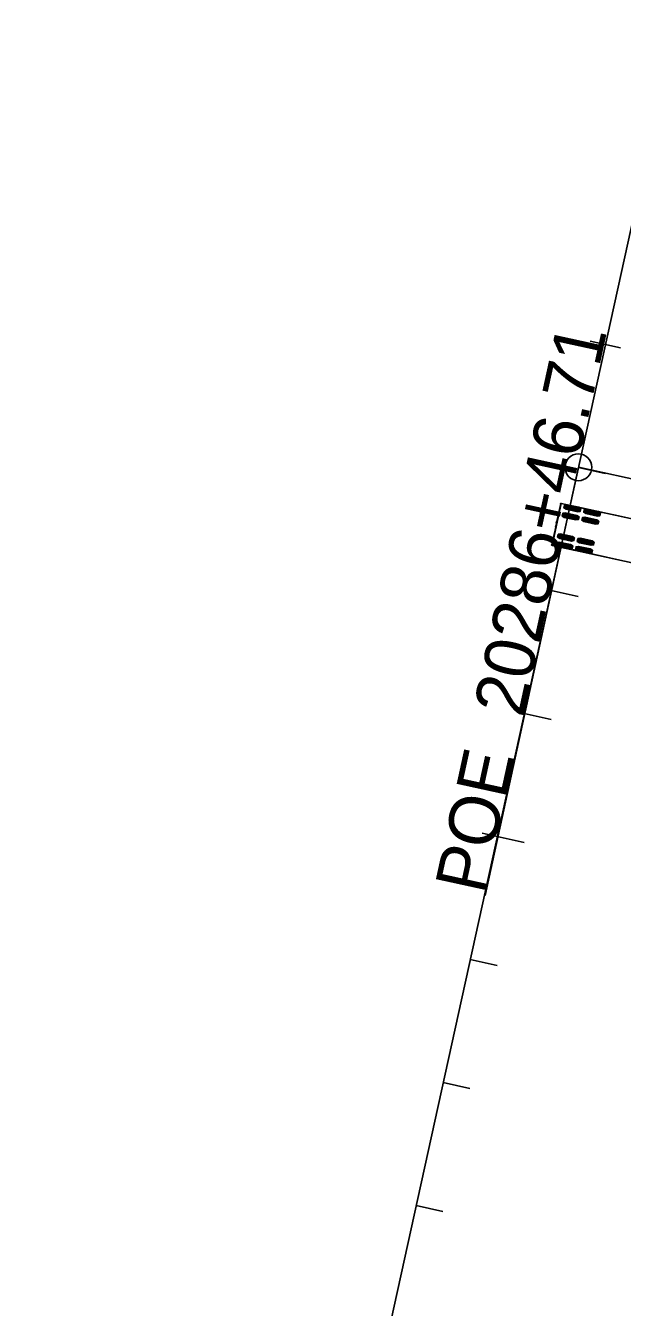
# Model space of a CAD drawing. Extents: x -69 to 14108008, y -6 to 8640172.
# Drawn here: x 14107547.9 to 14107666.4, y 8639300.8 to 8639555.2 of the extents above; entities that cross this region are included whole.
import ezdxf

# ---------------------------------------------------------------- set-up
doc = ezdxf.new("R2010")
doc.units = 0
for name, color, linetype in [('Alignment', 7, 'Continuous'), ('AutoTurn', 7, 'Continuous'), ('TextAlignment', 7, 'Continuous'), ('TextAlignmentLrg', 7, 'Continuous'), ('TextAlignmentSml', 7, 'Continuous')]:
    doc.layers.add(name, color=color, linetype=linetype)

msp = doc.modelspace()

# ---------------------------------------------------------------- linework, layer by layer
at = {"layer": 'Alignment'}
for p, q in [((14107732.61, 8639808.61), (14107547.95, 8638968.47)), ((14107858.63, 8639423.72), (14107657.65, 8639467.55))]:
    msp.add_line(p, q, dxfattribs=at)
at = {"layer": 'AutoTurn'}
for p, q in [((14107652.43, 8639452.05), (14107654.24, 8639460.36)), ((14107658.01, 8639458.83), (14107654.79, 8639459.54)), ((14107658.06, 8639459.06), (14107654.84, 8639459.76)), ((14107658.11, 8639459.28), (14107654.89, 8639459.98)), ((14107657.66, 8639457.22), (14107654.44, 8639457.92)), ((14107657.71, 8639457.44), (14107654.49, 8639458.15)), ((14107657.76, 8639457.67), (14107654.54, 8639458.37)), ((14107661.57, 8639456.37), (14107658.35, 8639457.07)), ((14107661.62, 8639456.59), (14107658.4, 8639457.3)), ((14107661.67, 8639456.82), (14107658.44, 8639457.52)), ((14107661.92, 8639457.98), (14107658.7, 8639458.68)), ((14107661.97, 8639458.2), (14107658.75, 8639458.91)), ((14107662.02, 8639458.43), (14107658.8, 8639459.13)), ((14107653.16, 8639455.7), (14107653.21, 8639455.96)), ((14107653.32, 8639456.47), (14107653.21, 8639455.97)), ((14107653.27, 8639456.22), (14107653.34, 8639456.21)), ((14107653.33, 8639456.48), (14107653.38, 8639456.74)), ((14107656.4, 8639451.42), (14107653.17, 8639452.13)), ((14107656.45, 8639451.65), (14107653.22, 8639452.35)), ((14107656.5, 8639451.87), (14107653.27, 8639452.57)), ((14107656.75, 8639453.04), (14107653.53, 8639453.74)), ((14107656.8, 8639453.26), (14107653.57, 8639453.96)), ((14107656.85, 8639453.48), (14107653.62, 8639454.19)), ((14107660.66, 8639452.18), (14107657.43, 8639452.89)), ((14107660.71, 8639452.41), (14107657.48, 8639453.11)), ((14107660.76, 8639452.63), (14107657.53, 8639453.33)), ((14107660.31, 8639450.57), (14107657.08, 8639451.27)), ((14107660.36, 8639450.8), (14107657.13, 8639451.5)), ((14107660.4, 8639451.02), (14107657.18, 8639451.72))]:
    msp.add_line(p, q, dxfattribs=at)
for points in [[(14107652.37, 8639452.09), (14107652.36, 8639452.07), (14107652.43, 8639452.05), (14107657.97, 8639450.85), (14107704.08, 8639440.79), (14107704.98, 8639444.94), (14107705.89, 8639449.1), (14107659.78, 8639459.15), (14107654.24, 8639460.36), (14107654.17, 8639460.37), (14107654.17, 8639460.35)], [(14107654.16, 8639460.33), (14107654.16, 8639460.33), (14107653.39, 8639456.78), (14107653.38, 8639456.74), (14107653.31, 8639456.76), (14107653.31, 8639456.75), (14107653.26, 8639456.49)], [(14107658.5, 8639459.43), (14107661.76, 8639458.72), (14107665.02, 8639458.01), (14107668.28, 8639457.3)], [(14107653.14, 8639455.98), (14107653.09, 8639455.72), (14107653.09, 8639455.72), (14107653.16, 8639455.7), (14107653.15, 8639455.67), (14107652.37, 8639452.12), (14107652.37, 8639452.11)], [(14107656.69, 8639451.13), (14107659.95, 8639450.41), (14107663.21, 8639449.7), (14107666.47, 8639448.99)]]:
    msp.add_lwpolyline(points, dxfattribs=at)
for points in [[(14107658.12, 8639459.34), (14107658, 8639458.78), (14107657.51, 8639458.71), (14107655.19, 8639459.21), (14107654.78, 8639459.48), (14107654.9, 8639460.04), (14107655.39, 8639460.11), (14107657.71, 8639459.6)], [(14107657.77, 8639457.72), (14107657.65, 8639457.17), (14107657.16, 8639457.1), (14107654.84, 8639457.6), (14107654.43, 8639457.87), (14107654.55, 8639458.43), (14107655.04, 8639458.5), (14107657.36, 8639457.99)], [(14107661.68, 8639456.87), (14107661.56, 8639456.31), (14107661.07, 8639456.24), (14107658.75, 8639456.75), (14107658.33, 8639457.02), (14107658.46, 8639457.58), (14107658.94, 8639457.65), (14107661.27, 8639457.14)], [(14107662.03, 8639458.48), (14107661.91, 8639457.93), (14107661.42, 8639457.86), (14107659.1, 8639458.36), (14107658.69, 8639458.63), (14107658.81, 8639459.19), (14107659.3, 8639459.26), (14107661.62, 8639458.75)], [(14107656.86, 8639453.54), (14107656.74, 8639452.98), (14107656.25, 8639452.91), (14107653.93, 8639453.42), (14107653.51, 8639453.68), (14107653.64, 8639454.24), (14107654.12, 8639454.31), (14107656.45, 8639453.81)], [(14107656.51, 8639451.93), (14107656.39, 8639451.37), (14107655.9, 8639451.3), (14107653.58, 8639451.8), (14107653.16, 8639452.07), (14107653.28, 8639452.63), (14107653.77, 8639452.7), (14107656.09, 8639452.19)], [(14107660.42, 8639451.07), (14107660.29, 8639450.52), (14107659.81, 8639450.45), (14107657.49, 8639450.95), (14107657.07, 8639451.22), (14107657.19, 8639451.78), (14107657.68, 8639451.85), (14107660, 8639451.34)], [(14107660.77, 8639452.69), (14107660.65, 8639452.13), (14107660.16, 8639452.06), (14107657.84, 8639452.56), (14107657.42, 8639452.83), (14107657.54, 8639453.39), (14107658.03, 8639453.46), (14107660.35, 8639452.95)]]:
    msp.add_lwpolyline(points, close=True, dxfattribs=at)
for centre, radius in [((14107654.13, 8639460.35), 0.0266), ((14107658.5, 8639459.43), 0.0417), ((14107652.34, 8639452.11), 0.0266), ((14107656.69, 8639451.13), 0.0417)]:
    msp.add_circle(centre, radius, dxfattribs=at)
for centre, radius, start, end in [((14107654.13, 8639460.35), 0.0363, 6.7758, 327.9371), ((14107653.18, 8639455.97), 0.0352, 348.6727, 167.6731), ((14107653.18, 8639455.97), 0.0354, 171.9899, 344.1753), ((14107653.29, 8639456.49), 0.0353, 351.0345, 169.3842), ((14107653.29, 8639456.49), 0.0352, 167.7236, 346.724), ((14107650.39, 8639452.52), 2.02, 347.6983, 348.3821)]:
    msp.add_arc(centre, radius, start, end, dxfattribs=at)
at = {"layer": 'TextAlignment'}
msp.add_line((14107657.65, 8639467.55), (14107639.11, 8639382.55), dxfattribs=at)
msp.add_circle((14107657.65, 8639467.55), 2.67, dxfattribs=at)
at = {"layer": 'TextAlignmentLrg'}
for p, q in [((14107665.99, 8639491.26), (14107660.01, 8639492.58)), ((14107641.53, 8639394.25), (14107646.87, 8639393.08))]:
    msp.add_line(p, q, dxfattribs=at)
at = {"layer": 'TextAlignmentSml'}
for p, q in [((14107665.99, 8639491.26), (14107660.01, 8639492.58)), ((14107657.64, 8639467.5), (14107662.97, 8639466.33)), ((14107652.27, 8639443.08), (14107657.6, 8639441.91)), ((14107646.9, 8639418.67), (14107652.23, 8639417.5)), ((14107644.52, 8639393.59), (14107638.55, 8639394.91)), ((14107636.17, 8639369.83), (14107641.5, 8639368.66)), ((14107630.8, 8639345.42), (14107636.13, 8639344.24)), ((14107625.43, 8639321), (14107630.77, 8639319.83))]:
    msp.add_line(p, q, dxfattribs=at)

# ---------------------------------------------------------------- texts
at = {"layer": 'TextAlignment'}
for s, p in [('20286+46.71', (14107646.58, 8639417.7)), ('POE ', (14107638.92, 8639382.59))]:
    msp.add_text(s, height=10.02, rotation=77.6983, dxfattribs=at).set_placement(p)

doc.saveas('drawing.dxf')
